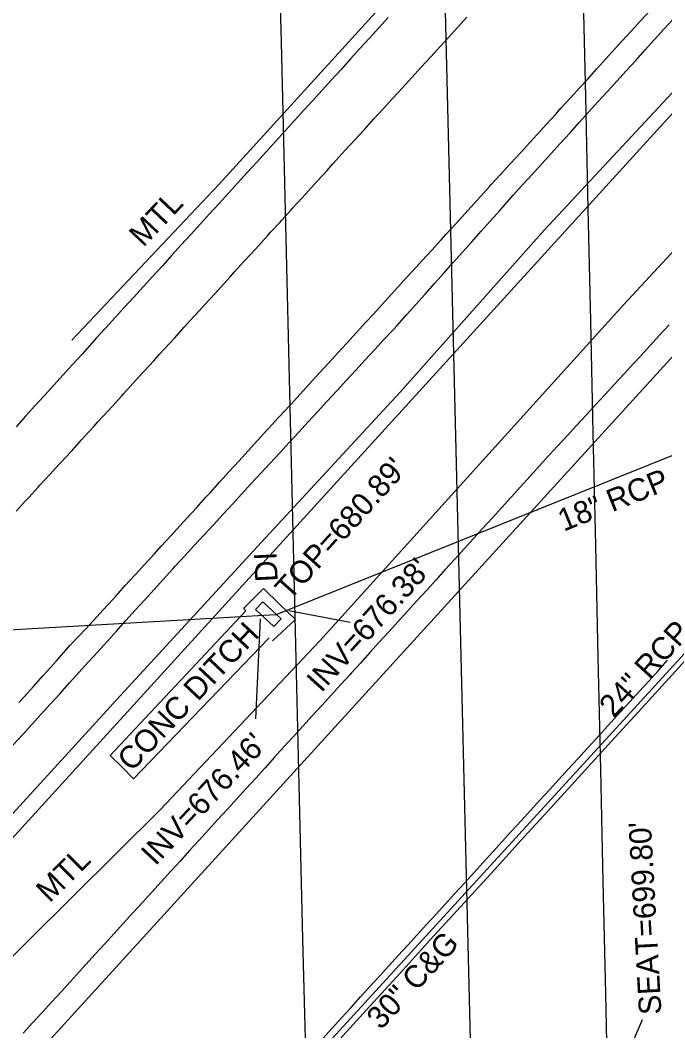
# Model space of a CAD drawing. Extents: x 1806071 to 1809844, y 912722 to 917035.
# Drawn here: x 1807747.2 to 1807862.1, y 914525.2 to 914705.5 of the extents above; entities that cross this region are included whole.
import ezdxf

# ---------------------------------------------------------------- set-up
doc = ezdxf.new("R2010")
doc.units = 0
for name, color, linetype in [('Exist Guardrail', 7, 'Continuous'), ('Exist Guardrail Text', 7, 'Continuous'), ('Exist Horizontal Alignment', 7, 'Continuous'), ('Exist Roads Curbs', 7, 'Continuous'), ('Exist Roads Curbs Text', 7, 'Continuous'), ('Exist Roads EOP', 7, 'Continuous'), ('Exist Roads EOT', 7, 'Continuous'), ('Exist Structure Major Bridge Seat Top Elevation', 7, 'Continuous'), ('Exist Structure Major Deck Tunnel Box Culvert', 7, 'Continuous'), ('Exist Structure Minor Drop Inlet', 7, 'Continuous'), ('Exist Structure Minor Drop Inlet Text', 7, 'Continuous'), ('Exist Structure Minor Drop Inlet Top Elevation', 7, 'Continuous'), ('Exist Structure Minor Paved Ditch or Gutter', 7, 'Continuous'), ('Exist Structure Minor Paved Ditch or Gutter Text', 7, 'Continuous'), ('Exist Structure Minor Pipes RCP 18 Inch', 7, 'Continuous'), ('Exist Structure Minor Pipes RCP 18 Inch Invert', 7, 'Continuous'), ('Exist Structure Minor Pipes RCP 18 Inch Text', 7, 'Continuous'), ('Exist Structure Minor Pipes RCP 24 Inch', 7, 'Continuous'), ('Exist Structure Minor Pipes RCP 24 Inch Text', 7, 'Continuous')]:
    doc.layers.add(name, color=color, linetype=linetype)

msp = doc.modelspace()

# ---------------------------------------------------------------- linework, layer by layer
at = {"layer": 'Exist Guardrail'}
for points in [[(1807756.38, 914648.41), (1807782.68, 914676.23), (1807805.14, 914700.91), (1807828.49, 914726.65), (1807851.81, 914751.97), (1807873.92, 914776.44), (1807904.72, 914809.73), (1807927.04, 914834.91), (1807952.45, 914863.76)], [(1807963.2, 914783.22), (1807935.17, 914760.04), (1807908.57, 914736.42), (1807882.27, 914710.65), (1807863.47, 914692.52), (1807840.66, 914668.07), (1807814.87, 914639.07), (1807789.47, 914611.6), (1807764.43, 914584.29), (1807738.95, 914556.51), (1807714.06, 914529.04), (1807691.49, 914504.04)], [(1807680.51, 914480.34), (1807706.97, 914502.99), (1807740.87, 914533.67), (1807772.15, 914564.62), (1807800.61, 914594.77), (1807854.85, 914654.76), (1807877.02, 914678.62), (1807893.92, 914697.43), (1807918.63, 914724.67), (1807943.49, 914751.73), (1807951.56, 914760.68)]]:
    msp.add_lwpolyline(points, dxfattribs=at)
at = {"layer": 'Exist Horizontal Alignment'}
for p, q in [((1806073.69, 912724.84), (1809374.2, 916346.52)), ((1807829.7, 914431.48), (1807805.85, 915414.67))]:
    msp.add_line(p, q, dxfattribs=at)
at = {"layer": 'Exist Roads Curbs'}
msp.add_lwpolyline([(1807798.75, 914517.79), (1807809.54, 914529.6), (1807814.92, 914535.51), (1807820.31, 914541.42), (1807825.7, 914547.33), (1807831.09, 914553.24), (1807836.48, 914559.14), (1807841.87, 914565.05), (1807847.26, 914570.96), (1807852.65, 914576.87), (1807858.04, 914582.78), (1807863.43, 914588.68), (1807868.82, 914594.59), (1807874.21, 914600.5), (1807879.6, 914606.39), (1807885.01, 914612.28), (1807890.42, 914618.17), (1807895.83, 914624.06), (1807901.22, 914629.98), (1807906.61, 914635.88), (1807911.99, 914641.8), (1807917.38, 914647.68), (1807922.71, 914653.67), (1807926.49, 914657.83)], dxfattribs=at)
at = {"layer": 'Exist Roads EOP'}
for points in [[(1807745.88, 914576.14), (1807747.56, 914577.99), (1807749.24, 914579.84), (1807750.91, 914581.7), (1807752.59, 914583.55), (1807754.27, 914585.4), (1807755.95, 914587.25), (1807757.63, 914589.11), (1807759.31, 914590.96), (1807760.99, 914592.81), (1807762.67, 914594.66), (1807764.34, 914596.52), (1807766.02, 914598.37), (1807767.7, 914600.22), (1807769.38, 914602.07), (1807771.06, 914603.93), (1807772.74, 914605.78), (1807774.42, 914607.63), (1807774.84, 914608.1), (1807776.54, 914609.94), (1807778.23, 914611.77), (1807779.92, 914613.61), (1807781.62, 914615.45), (1807783.31, 914617.29), (1807785.01, 914619.13), (1807786.7, 914620.97), (1807788.39, 914622.81), (1807790.09, 914624.64), (1807791.78, 914626.48), (1807793.47, 914628.32), (1807795.17, 914630.16), (1807796.86, 914632), (1807798.56, 914633.84), (1807800.25, 914635.68), (1807801.94, 914637.51), (1807803.64, 914639.35), (1807805.33, 914641.19), (1807807.03, 914643.03), (1807808.72, 914644.87), (1807810.41, 914646.71), (1807812.11, 914648.55), (1807813.8, 914650.38), (1807814.39, 914651.02), (1807816.06, 914652.89), (1807817.72, 914654.75), (1807819.38, 914656.62), (1807821.05, 914658.49), (1807822.71, 914660.35), (1807824.38, 914662.22), (1807826.04, 914664.08), (1807827.71, 914665.95), (1807829.37, 914667.81), (1807831.03, 914669.68), (1807832.7, 914671.54), (1807834.36, 914673.41), (1807835.09, 914674.23), (1807836.77, 914676.08), (1807838.46, 914677.93), (1807840.14, 914679.78), (1807841.82, 914681.63), (1807843.5, 914683.48), (1807845.18, 914685.33), (1807846.86, 914687.18), (1807848.54, 914689.03), (1807850.22, 914690.88), (1807851.9, 914692.74), (1807853.58, 914694.59), (1807855.27, 914696.44), (1807856.95, 914698.29), (1807858.63, 914700.14), (1807860.31, 914701.99), (1807861.99, 914703.84), (1807863.67, 914705.69)], [(1807812.81, 914705.95), (1807811.13, 914704.1), (1807809.45, 914702.25), (1807807.76, 914700.4), (1807806.08, 914698.55), (1807804.4, 914696.69), (1807802.72, 914694.84), (1807801.04, 914692.99), (1807799.36, 914691.14), (1807797.78, 914689.4), (1807796.1, 914687.55), (1807794.42, 914685.7), (1807792.73, 914683.85), (1807791.05, 914682), (1807789.37, 914680.16), (1807787.68, 914678.31), (1807786, 914676.46), (1807784.32, 914674.61), (1807782.63, 914672.76), (1807780.95, 914670.91), (1807779.27, 914669.06), (1807777.58, 914667.22), (1807775.9, 914665.37), (1807774.22, 914663.52), (1807772.53, 914661.67), (1807770.85, 914659.82), (1807769.17, 914657.97), (1807767.48, 914656.13), (1807765.8, 914654.28), (1807764.12, 914652.43), (1807762.44, 914650.58), (1807760.75, 914648.73), (1807759.88, 914647.77), (1807758.2, 914645.92), (1807756.52, 914644.07), (1807754.84, 914642.22), (1807753.16, 914640.37), (1807751.48, 914638.52), (1807749.8, 914636.66), (1807748.12, 914634.81), (1807746.44, 914632.96)], [(1807862.91, 914651.12), (1807861.22, 914649.28), (1807859.53, 914647.43), (1807857.84, 914645.59), (1807856.58, 914644.21), (1807854.88, 914642.37), (1807853.19, 914640.54), (1807851.5, 914638.7), (1807849.8, 914636.86), (1807848.11, 914635.02), (1807846.42, 914633.18), (1807844.72, 914631.34), (1807843.03, 914629.5), (1807841.48, 914627.81), (1807839.8, 914625.96), (1807838.12, 914624.11), (1807836.43, 914622.26), (1807834.75, 914620.41), (1807833.07, 914618.56), (1807831.39, 914616.71), (1807829.71, 914614.86), (1807828.03, 914613.01), (1807826.35, 914611.16), (1807824.67, 914609.31), (1807822.99, 914607.46), (1807821.3, 914605.61), (1807819.62, 914603.76), (1807817.94, 914601.91), (1807816.26, 914600.06), (1807814.58, 914598.21), (1807812.9, 914596.36), (1807811.22, 914594.51), (1807809.54, 914592.66), (1807807.86, 914590.81), (1807806.17, 914588.96), (1807806.01, 914588.77), (1807804.32, 914586.92), (1807802.64, 914585.08), (1807800.96, 914583.23), (1807799.27, 914581.38), (1807797.59, 914579.53), (1807795.91, 914577.68), (1807794.22, 914575.84), (1807792.54, 914573.99), (1807790.86, 914572.14), (1807789.17, 914570.29), (1807787.49, 914568.44), (1807785.81, 914566.59), (1807784.12, 914564.75), (1807782.44, 914562.9), (1807780.76, 914561.05), (1807779.07, 914559.2), (1807777.39, 914557.35), (1807775.71, 914555.5), (1807774.02, 914553.66), (1807772.34, 914551.81), (1807770.66, 914549.96), (1807768.97, 914548.11), (1807767.29, 914546.26), (1807765.61, 914544.41), (1807763.92, 914542.57), (1807762.24, 914540.72), (1807760.56, 914538.87), (1807758.87, 914537.02), (1807757.19, 914535.17), (1807756.15, 914534.03), (1807754.46, 914532.18), (1807752.77, 914530.34), (1807751.08, 914528.5), (1807749.39, 914526.65), (1807747.7, 914524.81)], [(1807801.13, 914523.86), (1807802.81, 914525.71), (1807804.5, 914527.55), (1807806.18, 914529.4), (1807807.87, 914531.25), (1807809.55, 914533.09), (1807811.24, 914534.94), (1807812.92, 914536.79), (1807814.61, 914538.64), (1807816.29, 914540.48), (1807817.98, 914542.33), (1807819.66, 914544.18), (1807821.34, 914546.02), (1807823.03, 914547.87), (1807824.71, 914549.72), (1807826.4, 914551.56), (1807828.08, 914553.41), (1807829.77, 914555.26), (1807831.45, 914557.11), (1807833.14, 914558.95), (1807834.82, 914560.8), (1807836.51, 914562.65), (1807838.19, 914564.49), (1807839.88, 914566.34), (1807841.56, 914568.19), (1807843.25, 914570.03), (1807844.93, 914571.88), (1807846.62, 914573.73), (1807848.3, 914575.58), (1807849.16, 914576.52), (1807850.84, 914578.36), (1807852.53, 914580.21), (1807854.21, 914582.06), (1807855.9, 914583.9), (1807857.58, 914585.75), (1807859.27, 914587.6), (1807860.95, 914589.44), (1807862.64, 914591.29)]]:
    msp.add_lwpolyline(points, dxfattribs=at)
at = {"layer": 'Exist Roads EOT'}
msp.add_line((1807617.6, 914375.74), (1808224.93, 915041.78), dxfattribs=at)
for points in [[(1807746.92, 914583.76), (1807747.88, 914584.8), (1807749.55, 914586.65), (1807751.23, 914588.5), (1807751.99, 914589.35), (1807753.65, 914591.21), (1807755.32, 914593.08), (1807756.11, 914593.97), (1807757.81, 914595.8), (1807759.51, 914597.63), (1807760.3, 914598.48), (1807761.99, 914600.32), (1807763.68, 914602.16), (1807764.23, 914602.76), (1807765.92, 914604.61), (1807767.6, 914606.46), (1807767.74, 914606.61), (1807769.42, 914608.45), (1807771.11, 914610.3), (1807772.32, 914611.63), (1807774.01, 914613.47), (1807775.7, 914615.32), (1807776.92, 914616.65), (1807778.6, 914618.5), (1807780.28, 914620.36), (1807781.09, 914621.25), (1807782.77, 914623.1), (1807784.45, 914624.95), (1807786.14, 914626.8), (1807787.82, 914628.65), (1807789.5, 914630.5), (1807791.19, 914632.35), (1807791.51, 914632.7), (1807793.19, 914634.54), (1807793.47, 914634.85), (1807795.22, 914636.65), (1807795.45, 914636.89), (1807797.12, 914638.74), (1807798.79, 914640.6), (1807800.52, 914642.53), (1807802.22, 914644.37), (1807803.91, 914646.21), (1807805.41, 914647.83), (1807807.09, 914649.68), (1807808.77, 914651.53), (1807810.04, 914652.93), (1807811.73, 914654.78), (1807813.41, 914656.62), (1807814.47, 914657.78), (1807816.16, 914659.62), (1807817.85, 914661.46), (1807818.89, 914662.59), (1807820.57, 914664.44), (1807822.25, 914666.3), (1807823.11, 914667.25), (1807824.79, 914669.09), (1807826.48, 914670.93), (1807827.6, 914672.16), (1807829.27, 914674.02), (1807830.95, 914675.87), (1807831.12, 914676.07), (1807832.81, 914677.92), (1807834.5, 914679.76), (1807834.69, 914679.96), (1807836.38, 914681.81), (1807838.06, 914683.65), (1807839.37, 914685.08), (1807841.06, 914686.93), (1807842.74, 914688.77), (1807843.63, 914689.74), (1807845.31, 914691.58), (1807847, 914693.43), (1807848.33, 914694.88), (1807849.99, 914696.74), (1807851.66, 914698.61), (1807852.79, 914699.87), (1807854.48, 914701.71), (1807856.13, 914703.51), (1807857.83, 914705.35), (1807859.53, 914707.18)], [(1807746.92, 914583.76), (1807747.88, 914584.8), (1807749.55, 914586.65), (1807751.23, 914588.5), (1807751.99, 914589.35), (1807753.65, 914591.21), (1807755.32, 914593.08), (1807756.11, 914593.97), (1807757.81, 914595.8), (1807759.51, 914597.63), (1807760.3, 914598.48), (1807761.99, 914600.32), (1807763.68, 914602.16), (1807764.23, 914602.76), (1807765.92, 914604.61), (1807767.6, 914606.46), (1807767.74, 914606.61), (1807769.42, 914608.45), (1807771.11, 914610.3), (1807772.32, 914611.63), (1807774.01, 914613.47), (1807775.7, 914615.32), (1807776.92, 914616.65), (1807778.6, 914618.5), (1807780.28, 914620.36), (1807781.09, 914621.25), (1807782.77, 914623.1), (1807784.45, 914624.95), (1807786.14, 914626.8), (1807787.82, 914628.65), (1807789.5, 914630.5), (1807791.19, 914632.35), (1807791.51, 914632.7), (1807793.19, 914634.54), (1807793.47, 914634.85), (1807795.22, 914636.65), (1807795.45, 914636.89), (1807797.12, 914638.74), (1807798.79, 914640.6), (1807800.52, 914642.53), (1807802.22, 914644.37), (1807803.91, 914646.21), (1807805.41, 914647.83), (1807807.09, 914649.68), (1807808.77, 914651.53), (1807810.04, 914652.93), (1807811.73, 914654.78), (1807813.41, 914656.62), (1807814.47, 914657.78), (1807816.16, 914659.62), (1807817.85, 914661.46), (1807818.89, 914662.59), (1807820.57, 914664.44), (1807822.25, 914666.3), (1807823.11, 914667.25), (1807824.79, 914669.09), (1807826.48, 914670.93), (1807827.6, 914672.16), (1807829.27, 914674.02), (1807830.95, 914675.87), (1807831.12, 914676.07), (1807832.81, 914677.92), (1807834.5, 914679.76), (1807834.69, 914679.96), (1807836.38, 914681.81), (1807838.06, 914683.65), (1807839.37, 914685.08), (1807841.06, 914686.93), (1807842.74, 914688.77), (1807843.63, 914689.74), (1807845.31, 914691.58), (1807847, 914693.43), (1807848.33, 914694.88), (1807849.99, 914696.74), (1807851.66, 914698.61), (1807852.79, 914699.87), (1807854.48, 914701.71), (1807856.13, 914703.51), (1807857.83, 914705.35), (1807859.53, 914707.18)], [(1807746.44, 914617.88), (1807748.13, 914619.72), (1807748.69, 914620.33), (1807750.39, 914622.17), (1807750.7, 914622.51), (1807752.44, 914624.41), (1807754.13, 914626.25), (1807754.51, 914626.67), (1807756.21, 914628.5), (1807756.43, 914628.74), (1807758.1, 914630.6), (1807758.65, 914631.21), (1807760.34, 914633.06), (1807761.1, 914633.9), (1807762.8, 914635.73), (1807763.63, 914636.62), (1807765.31, 914638.47), (1807765.61, 914638.8), (1807767.34, 914640.7), (1807769.01, 914642.56), (1807769.3, 914642.89), (1807770.99, 914644.73), (1807772.04, 914645.88), (1807773.73, 914647.72), (1807774.75, 914648.83), (1807776.41, 914650.69), (1807777.45, 914651.86), (1807779.15, 914653.69), (1807780.19, 914654.81), (1807781.87, 914656.66), (1807782.93, 914657.83), (1807784.6, 914659.69), (1807785.38, 914660.56), (1807787.07, 914662.4), (1807787.37, 914662.72), (1807789.06, 914664.57), (1807789.61, 914665.17), (1807791.29, 914667.02), (1807791.83, 914667.63), (1807793.54, 914669.46), (1807793.82, 914669.77), (1807795.5, 914671.62), (1807795.76, 914671.91), (1807797.44, 914673.77), (1807797.99, 914674.39), (1807799.68, 914676.24), (1807800.21, 914676.82), (1807801.9, 914678.67), (1807802.94, 914679.81), (1807804.62, 914681.67), (1807805.2, 914682.31), (1807806.89, 914684.15), (1807808.57, 914685.99), (1807810.26, 914687.84), (1807811.95, 914689.68), (1807813.64, 914691.52), (1807815.33, 914693.37), (1807817.02, 914695.21), (1807818.71, 914697.05), (1807820.39, 914698.9), (1807822.08, 914700.74), (1807823.51, 914702.3), (1807825.18, 914704.16), (1807826.86, 914706.02)]]:
    msp.add_lwpolyline(points, dxfattribs=at)
at = {"layer": 'Exist Structure Major Bridge Seat Top Elevation'}
msp.add_line((1807854.84, 914519.55), (1807858.18, 914527.21), dxfattribs=at)
at = {"layer": 'Exist Structure Major Deck Tunnel Box Culvert'}
for points in [[(1807798.09, 914521.58), (1807797.61, 914541.57), (1807797.13, 914561.57), (1807796.64, 914581.56), (1807796.16, 914601.56), (1807795.68, 914621.55), (1807795.2, 914641.54), (1807794.71, 914661.54), (1807794.23, 914681.53), (1807793.75, 914701.53), (1807793.27, 914721.52)], [(1807847.54, 914711.78), (1807847.99, 914691.79), (1807848.43, 914671.79), (1807848.87, 914651.8), (1807849.32, 914631.8), (1807849.76, 914611.81), (1807850.21, 914591.81), (1807850.65, 914571.82), (1807851.1, 914551.82), (1807851.54, 914531.83), (1807851.93, 914514.46)]]:
    msp.add_lwpolyline(points, dxfattribs=at)
at = {"layer": 'Exist Structure Minor Drop Inlet'}
msp.add_lwpolyline([(1807789.16, 914600.34), (1807792.4, 914597.32), (1807793.7, 914598.71), (1807790.46, 914601.73)], close=True, dxfattribs=at)
at = {"layer": 'Exist Structure Minor Paved Ditch or Gutter'}
for points in [[(1807787.44, 914600.13), (1807787.03, 914600.58), (1807790.54, 914604.09), (1807793.42, 914601.33), (1807796.29, 914598.59), (1807792.18, 914594.78)], [(1807787.44, 914600.13), (1807763.2, 914574.33), (1807765.35, 914572.21), (1807767.4, 914570.18), (1807791.56, 914595.29)]]:
    msp.add_lwpolyline(points, dxfattribs=at)
at = {"layer": 'Exist Structure Minor Pipes RCP 18 Inch'}
for q in [(1807915.84, 914648.84), (1807695.95, 914593.87)]:
    msp.add_line((1807792.71, 914599.43), q, dxfattribs=at)
at = {"layer": 'Exist Structure Minor Pipes RCP 18 Inch Invert'}
for p, q in [((1807795.09, 914600.19), (1807806.02, 914598.11)), ((1807789.98, 914598.7), (1807789.13, 914580.86))]:
    msp.add_line(p, q, dxfattribs=at)
at = {"layer": 'Exist Structure Minor Pipes RCP 24 Inch'}
msp.add_line((1807747.99, 914463.93), (1807915.73, 914647.29), dxfattribs=at)

# ---------------------------------------------------------------- texts
at = {"layer": 'Exist Guardrail Text'}
for rotation, p in [(46.6137, (1807769.14, 914664.82)), (44.7033, (1807752.42, 914547.91))]:
    msp.add_text('MTL', height=4, rotation=rotation, dxfattribs=at).set_placement(p)
at = {"layer": 'Exist Roads Curbs Text'}
msp.add_text('30" C&G', height=4, rotation=47.4413, dxfattribs=at).set_placement((1807811.53, 914525.24))
at = {"layer": 'Exist Structure Major Bridge Seat Top Elevation'}
msp.add_text("SEAT=699.80'", height=4, rotation=93.1745, dxfattribs=at).set_placement((1807861.56, 914528.18))
at = {"layer": 'Exist Structure Minor Drop Inlet Text'}
msp.add_text('DI', height=4, rotation=92.8422, dxfattribs=at).set_placement((1807793.12, 914605.35))
at = {"layer": 'Exist Structure Minor Drop Inlet Top Elevation'}
msp.add_text("TOP=680.89'", height=4, rotation=47.9554, dxfattribs=at).set_placement((1807795.24, 914601.8))
at = {"layer": 'Exist Structure Minor Paved Ditch or Gutter Text'}
msp.add_text('CONC DITCH', height=4, rotation=46.784, dxfattribs=at).set_placement((1807767.05, 914571.27))
at = {"layer": 'Exist Structure Minor Pipes RCP 18 Inch Invert'}
for s, rotation, p in [("INV=676.38'", 47.9305, (1807800.88, 914585.38)), ("INV=676.46'", 47.0035, (1807771.3, 914554.49))]:
    msp.add_text(s, height=4, rotation=rotation, dxfattribs=at).set_placement(p)
at = {"layer": 'Exist Structure Minor Pipes RCP 18 Inch Text'}
msp.add_text('18" RCP', height=4, rotation=21.8648, dxfattribs=at).set_placement((1807844.09, 914614.21))
at = {"layer": 'Exist Structure Minor Pipes RCP 24 Inch Text'}
msp.add_text('24" RCP', height=4, rotation=47.5473, dxfattribs=at).set_placement((1807853.02, 914580.88))

doc.saveas('drawing.dxf')
